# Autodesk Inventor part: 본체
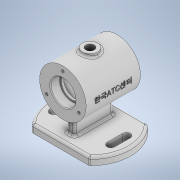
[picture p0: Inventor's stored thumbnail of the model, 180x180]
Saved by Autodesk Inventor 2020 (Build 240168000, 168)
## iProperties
Created: 2021-09
Part Number: 본체
Material: 일반
Document SubType Name: Modeling
Designer: Administrator
Density: 1 g/cm^3
Appearance: 기본값
Mass: 173.238 g
Surface Area: 487.435 cm^2
Volume: 173.238 cm^3
Author: Administrator
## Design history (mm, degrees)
sketch "스케치1"
  geometry: L1 (52.5, 0)-(-52.5, 0); L2 (36.742, -37.5)-(-36.742, -37.5); L3 (36.742, 37.5)-(-36.742, 37.5); A1 r 52.5 centre (0, 0) between (52.5, 0) and (-52.5, 0); 2 further points
  constraints: 6 end point, 6 point on circle, 2 coincident, 2 parallel, 1 centre point, 1 horizontal, 1 midpoint
  dimensions: "d0" = 105 diameter of A1; "d1" = 37.5 distance between parallel lines of L1 L2; "d2" = 37.5 distance between parallel lines of L1 L3
extrude "돌출1" new body sketch "스케치1" distance "d3" = 10; taper "d4" = 0 deg
sketch "스케치2"
  geometry: L1 (-37, -10)-(-37, 10); L2 (-32, -10)-(-32, 10); L3 (-42, 10)-(-42, -10); L4 (-36.742, -37.5)-(36.742, -37.5) reference; L5 (0, -37.5)-(0, 37.5); L6 (36.742, 37.5)-(-36.742, 37.5) reference; L7 (32, -10)-(32, 10); L8 (42, 10)-(42, -10); A1 r 5 centre (-37, -10) between (-42, -10) and (-32, -10); A2 r 5 centre (-37, 10) between (-32, 10) and (-42, 10); A3 r 5 centre (37, 10) between (42, 10) and (32, 10); A4 r 5 centre (37, -10) between (32, -10) and (42, -10); 2 further points
  constraints: 14 end point, 8 point on circle, 6 symmetric about line, 4 centre point, 4 tangent, 3 midpoint, 1 horizontal alignment, 1 parallel, 1 vertical, 2 other
  dimensions: "d5" = 20 distance of L1.end L1.start; "d6" = 37 distance of point (-37, 0) point (0, 0); "d7" = 10 distance from line of L2.end L3
extrude "돌출2" cut sketch "스케치2" extent not by distance; stored distance "d8" = 0; taper "d9" = 0 deg
sketch "스케치3"
  geometry: C1 r 30 at (0, 62); 1 further point
  constraints: 1 centre point, 1 vertical alignment
  dimensions: "d10" = 60 diameter of C1; "d11" = 62 distance of point (0, 0) C1.centre
extrude "돌출3" join sketch "스케치3" stored distance "d12" = 70; taper "d13" = 0 deg
sketch "스케치4"
  geometry: L1 (62, 25)-(0, 25); L2 (0, 25)-(0, -25); L3 (0, -25)-(62, -25); L4 (62, -25)-(62, 25); L5 (0, 10)-(0, -10) reference; L6 (0, -37.5)-(10, -37.5) reference; 1 further point
  constraints: 8 end point, 2 parallel, 1 collinear, 1 horizontal, 1 perpendicular
  dimensions: "d14" = 50 distance between parallel lines of L3 L1; "d15" = 12.5 distance between parallel lines of L6 L3; "d16" = 62 distance between parallel lines of L2 L4
extrude "돌출4" join sketch "스케치4" stored distance "d17" = 10; taper "d18" = 0 deg
node "작업 평면2"
  node "작업 평면1"
sketch "스케치5"
  geometry: C1 r 10 at (0, 0); 1 further point
  constraints: 1 centre point, 1 coincident
  dimensions: "d20" = 20 diameter of C1
extrude "돌출5" join sketch "스케치5" distance "d21" = 33; taper "d22" = 0 deg
sketch "스케치6"
  geometry: L1 (92, 35)-(32, 35) reference; L2 (62, 35)-(62, -35); L3 (32, -35)-(92, -35) reference; L4 (62, 35)-(78, 35); L5 (78, 35)-(78, 23); L6 (78, 23)-(76, 23); L7 (76, 23)-(76, 20); L8 (76, 20)-(87, 20); L9 (87, 20)-(87, -20); L10 (87, -20)-(76, -20); L11 (76, -20)-(76, -23); L12 (76, -23)-(78, -23); L13 (78, -23)-(78, -35); L14 (78, -35)-(62, -35); 1 further point
  constraints: 24 end point, 8 perpendicular, 2 midpoint, 2 point on line, 1 collinear, 1 vertical
  dimensions: "d23" = 28 diameter of L7 L2; "d24" = 32 diameter of L5 L2; "d25" = 50 diameter of L9 L2; "d26" = 28 diameter of L11 L2; "d27" = 32 diameter of L13 L2; "d28" = 12 distance from line of L14 L12.end; "d29" = 3 distance from line of L10 L12.end; "d30" = 3 distance from line of L5.end L8; "d31" = 40 distance between parallel lines of L10 L8
revolve "회전1" sketch "스케치6" stored, may be unused: angle "d32" = 90 deg
sketch "스케치7"
  geometry: C1 r 10 at (0, 0) reference; 2 further points
  constraints: 1 coincident
hole "구멍1" sketch "스케치7" at (0, 0) diameter "d33" = 10.917; stored, may be unused: countersink angle "d37" = 90 deg, drill point angle "d39" = 118 deg; dims "d34" = 20, "d35" = 4, "d36" = 2, "d38" = 21
sketch "스케치8" dims "d40" = 48
  geometry: C1 r 30 at (0, 0) reference; 3 further points
  constraints: 2 vertical alignment, 1 coincident, 2 other
hole "구멍2" sketch "스케치8" at (0, 24) diameter "d41" = 3.45873; stored, may be unused: countersink angle "d45" = 90 deg, drill point angle "d47" = 118 deg; dims "d42" = 8, "d43" = 4, "d44" = 2, "d46" = 10
fillet "모깎기1" dims "d51" = 0.3
chamfer "모따기3" distance "d58" = 1; stored, may be unused: second distance "d59" = 2, angle "d60" = 45 deg
chamfer "모따기4" distance "d61" = 1; stored, may be unused: second distance "d62" = 2, angle "d63" = 45 deg
fillet "모깎기2" dims "d64" = 3
node "작업 평면4"
  node "작업 평면3"
sketch "스케치9"
  geometry: L1 (30, -35)-(30, 35) reference; L2 (30, 35)-(-30, 35) reference; 2 further points
  constraints: 1 other
  dimensions: "d66" = 35 distance from line of point (0, 0) L2; "d67" = 30 distance from line of L1 point (0, 0)
feature "엠보싱1" sketch "스케치9" dims "d5" = 20, "d6" = 37, "d7" = 10, "d68" = 0.5, "d69" = 0
node "솔리드1"
pattern_circular "원형 패턴1" dims angle "d49" = 360 deg
mirror "미러1"
feature "A9D066F2-1C7D-4E18-AEED-F7BC21143FA4" dims "d33" = 10.917, "d34" = 20, "d35" = 4, "d36" = 2, "d37" = 90 deg, "d38" = 21, "d39" = 118 deg
other parameters: "d19" = 3
